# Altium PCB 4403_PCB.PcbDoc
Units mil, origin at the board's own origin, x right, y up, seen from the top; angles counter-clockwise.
Board outline 547.34 x 948.91 mil, 4 copper layers (Top Layer, Signal Layer 1, Signal Layer 2, Bottom Layer), stack 30.634 mil thick; 38 components, 56 nets, 193 pads, 89 vias.
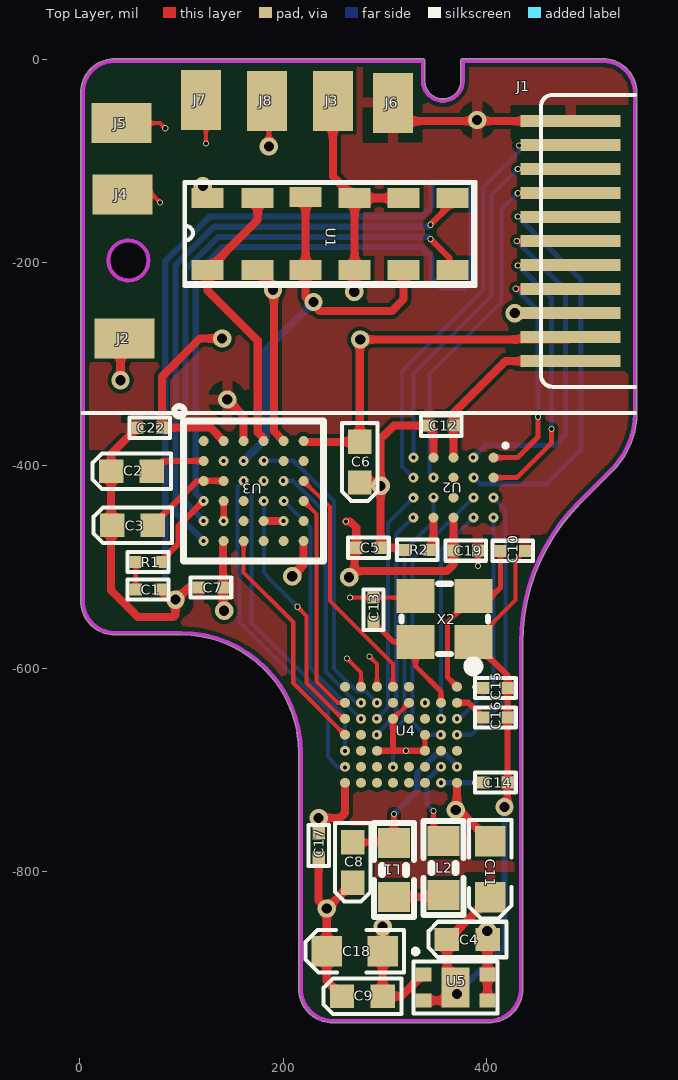
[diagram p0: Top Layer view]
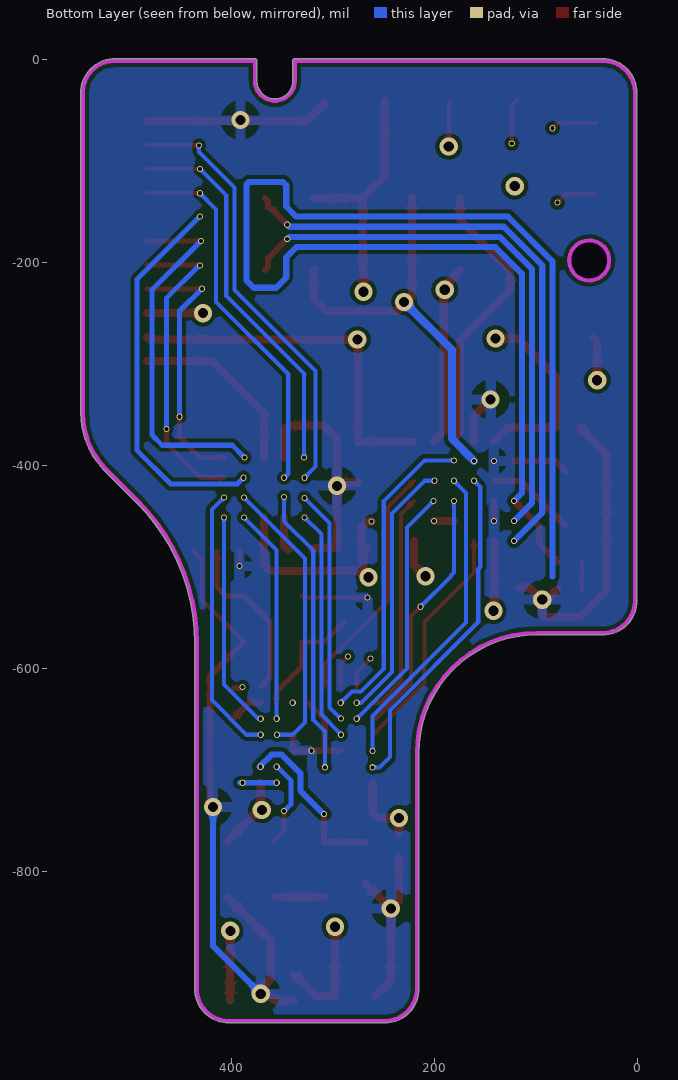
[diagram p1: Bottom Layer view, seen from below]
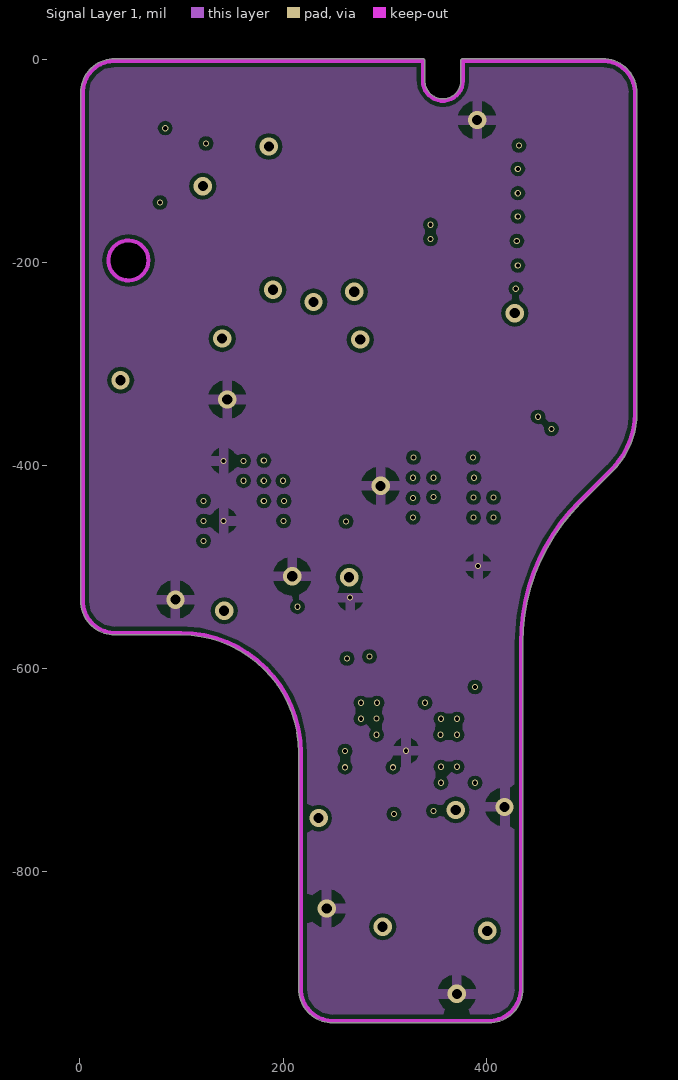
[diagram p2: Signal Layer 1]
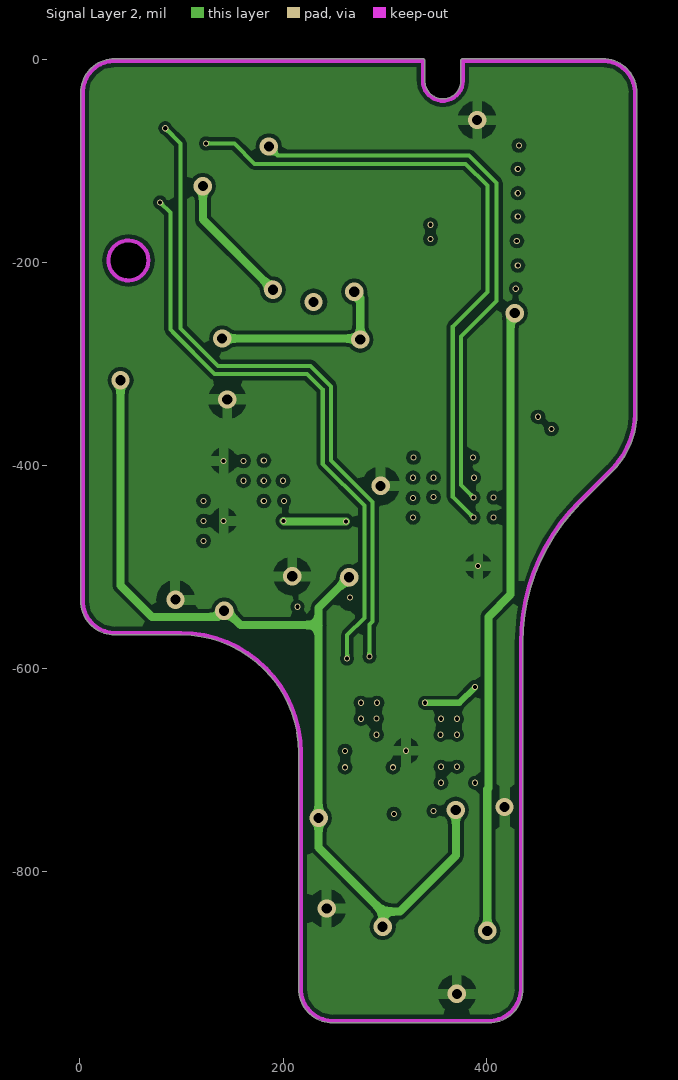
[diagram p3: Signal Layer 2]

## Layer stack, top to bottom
Top Solder: solder mask 0.4, Solder Resist, Dk 3.5
Top Layer: signal copper 1.4
Dielectric 1: core 10, FR-4, Dk 4.2
Signal Layer 1: signal copper 1.417
Dielectric 3: prepreg 5, Dk 4.2
Signal Layer 2: signal copper 1.417
Dielectric 4: core 10, Dk 4.2
Bottom Layer: signal copper 1.4
Bottom Solder: solder mask 0.4, Solder Resist, Dk 3.5

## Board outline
34.38,-566.67 99.34,-566.67 cw(c99.34,-682.77) 215.44,-682.77 215.44,-915.05 ccw(c248.95,-915.05) 248.95,-948.56 402.49,-948.56 ccw(c402.49,-915.05) 436,-915.05 ccw(c433.99,-915.05) 436,-915.03 436,-574.54 cw(c630.84,-574.54) 493.06,-436.79 cw(c630.84,-574.54) 493.07,-436.77 ccw(c491.64,-435.35) 493.08,-436.77 493.07,-436.77 524.56,-405.29 ccw(c467.45,-348.19) 548.21,-348.19 ccw(c546.19,-348.19) 548.21,-348.19 ccw(c546.19,-348.19) 548.21,-348.15 ccw(c546.19,-348.12) 548.21,-348.12 548.21,-33.16 ccw(c514.7,-33.16) 514.7,0.35 376.9,0.35 ccw(c376.9,-1.67) 374.89,-1.67 374.89,-21.35 ccw(c376.9,-21.35) 374.89,-21.37 ccw(c357.22,-21.35) 374.89,-21.35 374.89,-21.37 cw(c357.22,-21.35) 339.55,-21.35 339.55,-1.67 ccw(c337.53,-1.67) 337.53,0.35 34.38,0.35 ccw(c34.38,-33.16) 0.87,-33.16 ccw(c2.89,-33.16) 0.87,-33.18 0.87,-533.16 ccw(c34.38,-533.16)
cut-out: 47.77,-217.81 cw(c47.77,-198.12) 28.08,-198.12 cw(c47.77,-198.12) 47.77,-178.44 cw(c47.77,-198.12) 67.45,-198.12 cw(c47.77,-198.12)

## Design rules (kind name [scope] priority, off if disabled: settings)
Clearance [All] p1: gap=4 ignorepadtopadclearanceinfootprint=FALSE except(0: Arc-Hole Track-Hole SMDPad-Hole THPad-Hole Via-Hole Fill-Hole Poly-Hole Region-Hole Text-Hole)
DiffPairsRouting DiffPair_DiffPairsRouting [InDifferentialPair ('D_DET')] p1: maxlimit=4 minlimit=4 mostfreqgap=4 toplayer_minwidth=6 toplayer_maxwidth=6 toplayer_prefwidth=6 midlayer1_minwidth=6 midlayer1_maxwidth=6 midlayer1_prefwidth=6 midlayer2_minwidth=6 midlayer2_maxwidth=6 midlayer2_prefwidth=6 bottomlayer_minwidth=6 bottomlayer_maxwidth=6 bottomlayer_prefwidth=6 maxuncoupledlength=500
DiffPairsRouting DiffPair_DiffPairsRouting_1 [InDifferentialPair ('D_DET')] p2: maxlimit=4 minlimit=4 mostfreqgap=4 toplayer_minwidth=6 toplayer_maxwidth=6 toplayer_prefwidth=6 midlayer1_minwidth=6 midlayer1_maxwidth=6 midlayer1_prefwidth=6 midlayer2_minwidth=6 midlayer2_maxwidth=6 midlayer2_prefwidth=6 bottomlayer_minwidth=6 bottomlayer_maxwidth=6 bottomlayer_prefwidth=6 maxuncoupledlength=500
DiffPairsRouting DiffPair_DiffPairsRouting_3 [InDifferentialPair ('D_DET')] p3: maxlimit=4 minlimit=4 mostfreqgap=4 toplayer_minwidth=6 toplayer_maxwidth=6 toplayer_prefwidth=6 midlayer1_minwidth=6 midlayer1_maxwidth=6 midlayer1_prefwidth=6 midlayer2_minwidth=6 midlayer2_maxwidth=6 midlayer2_prefwidth=6 bottomlayer_minwidth=6 bottomlayer_maxwidth=6 bottomlayer_prefwidth=6 maxuncoupledlength=500
DiffPairsRouting DiffPairsRouting_1 [InDifferentialPair ('D_DET')] p4: maxlimit=10 minlimit=10 mostfreqgap=10 toplayer_minwidth=15 toplayer_maxwidth=15 toplayer_prefwidth=15 midlayer1_minwidth=15 midlayer1_maxwidth=15 midlayer1_prefwidth=15 midlayer2_minwidth=15 midlayer2_maxwidth=15 midlayer2_prefwidth=15 bottomlayer_minwidth=15 bottomlayer_maxwidth=15 bottomlayer_prefwidth=15 maxuncoupledlength=500
DiffPairsRouting DiffPair_DiffPairsRouting_2 [InDifferentialPair ('DET_')] p5: maxlimit=4 minlimit=4 mostfreqgap=4 toplayer_minwidth=6 toplayer_maxwidth=6 toplayer_prefwidth=6 midlayer1_minwidth=6 midlayer1_maxwidth=6 midlayer1_prefwidth=6 midlayer2_minwidth=6 midlayer2_maxwidth=6 midlayer2_prefwidth=6 bottomlayer_minwidth=6 bottomlayer_maxwidth=6 bottomlayer_prefwidth=6 maxuncoupledlength=500
DiffPairsRouting [All] p6: maxlimit=10 minlimit=10 mostfreqgap=10 toplayer_minwidth=15 toplayer_maxwidth=15 toplayer_prefwidth=15 midlayer1_minwidth=15 midlayer1_maxwidth=15 midlayer1_prefwidth=15 midlayer2_minwidth=15 midlayer2_maxwidth=15 midlayer2_prefwidth=15 bottomlayer_minwidth=15 bottomlayer_maxwidth=15 bottomlayer_prefwidth=15 maxuncoupledlength=500
MatchedLengths DiffPair_MatchedLengths [InDifferentialPair ('D_DET')] p1: tolerance=1000 checknetsindiffpair=FALSE checkdiffpairvsdiffpair=TRUE checkxsignals=TRUE checkothers=TRUE
MatchedLengths DiffPair_MatchedLengths_1 [InDifferentialPair ('D_DET')] p2: tolerance=1000 checknetsindiffpair=FALSE checkdiffpairvsdiffpair=TRUE checkxsignals=TRUE checkothers=TRUE
MatchedLengths DiffPair_MatchedLengths_3 [InDifferentialPair ('D_DET')] p3: tolerance=1000 checknetsindiffpair=FALSE checkdiffpairvsdiffpair=TRUE checkxsignals=TRUE checkothers=TRUE
MatchedLengths [InDifferentialPair ('D_DET')] p4: tolerance=1000 checknetsindiffpair=FALSE checkdiffpairvsdiffpair=TRUE checkxsignals=TRUE checkothers=TRUE
MatchedLengths DiffPair_MatchedLengths_2 [InDifferentialPair ('DET_')] p5: tolerance=1000 checknetsindiffpair=FALSE checkdiffpairvsdiffpair=TRUE checkxsignals=TRUE checkothers=TRUE
PolygonConnect [All] p1: connectstyle=Relief reliefconductorwidth=10 reliefentries=4 polygonreliefangle="90 Angle" airgapwidth=10
RoutingVias [All] p1: holewidth=28 width=50 viastyle="Through Hole" minholewidth=4 minwidth=10 maxholewidth=28 maxwidth=50
SolderMaskExpansion [All] p1: expansion=4 istentingtop=FALSE
Width [All] p1: maxlimit=100 minlimit=4 preferedwidth=10
29 further rules are at their usual default settings.

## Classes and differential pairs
component class 4403: C1 C2 C3 C5 C6 C7 C12 C19 C22 R1 R2 U1 U2
component class pca10040_sheet1_radio: C8 C10 C11 C13 C14 C15 C16 C17 L1 L2 U4 X2
component class POWER: C4 C9 C18 J1 J2 J3 J4 J5 J6 J7 J8 U5
differential pair D_DET: +DET_P -DET_N

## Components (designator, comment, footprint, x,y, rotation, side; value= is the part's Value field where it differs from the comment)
C1 "0.01uF" 0201 79,-522 r180 top
C2 "2.2uF" 0402 50.49,-405.25 r0 top
C3 "2.2uF" 0402 51.49,-458.25 r0 top
C4 "1.0uF" 0402 381,-866 r0 top
C5 "0.1uF" 0201 296,-481 r180 top
C6 "1.0uF" 0402 275,-397 r90 top
C7 "0.1uF" 0201 117,-520 r0 top
C8 "1.0uF" 0402 268,-791 r90 top
C9 "1.0uF" 0402 277.75,-921.74 r0 top
C10 "12pF" 0201 438,-484 r180 top
C11 "4.7" 0603 404,-825 r90 top
C12 "0.1uF" 0201 343.75,-360.74 r0 top
C13 "12pF" 0201 289,-530 r270 top
C14 "0.1uF" 0201 421,-712 r180 top
C15 "100pF" 0201 421,-619 r180 top
C16 "100pF" 0201 421,-648 r180 top
C17 "0.1uF" 0201 235,-786 r90 top
C18 "10uF" 0603 243,-878 r0 top
C19 "0.1uF" 0201 391.75,-483.74 r180 top
C22 "0.1uF" 0201 56.75,-362.74 r0 top
J1 "J11" J11 483,-61 r0 top
J2 "PAD" PAD1.5 43.75,-274.74 r0 top
J3 "PAD" PAD1.5 249,-41 r90 top
J4 "PAD" PAD1.5 42,-133 r0 top
J5 "PAD" PAD1.5 41,-63 r0 top
J6 "PAD" PAD1.5 308,-43 r90 top
J7 "PAD" PAD1.5 119,-40 r90 top
J8 "PAD" PAD1.5 184,-41 r90 top
L1 "15nH" INDC1608X06L 309,-798 r90 top
L2 "10uH" INDC1608X06L 358,-796 r270 top
R1 "1K" 0201 55,-495 r0 top
R2 "10K" 0201 320,-483 r0 top
U1 "SRH_7060" SRH_7060 125.75,-136.74 r90 top
U2 "TXB0108_YZP_20" BGA20C50P4X5_189X239X50 367.75,-421.74 r270 top
U3 "AFE4403" BGA36C50P6X6_304X304X50 171,-425 r0 top
U4 "NRF52832_WLCS" BGA56C40P7X8_300X320X38 316,-665 r270 top
U5 "XC6221A332GR" USP-4 369.75,-913.74 r0 top
X2 "32MHz" BT-XTAL_2016 359,-551 r0 top

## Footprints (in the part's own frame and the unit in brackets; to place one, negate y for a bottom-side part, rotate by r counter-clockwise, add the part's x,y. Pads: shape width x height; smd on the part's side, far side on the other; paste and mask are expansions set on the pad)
0201 [mil]
  rect 12x12 smd: 1(0,0) 2(24,0)
  silkscreen extent -8,-10 32,10, body extent 0,-6 24,6, height 12
0402 [mil]
  rect 24x23 smd: 1(-19.74,-0.49) 2(20.26,-0.49)
  silkscreen extent -38,-18 39,17, body extent -19,-10 21,10, height 20
0603 [mil]
  rect 30x30 smd: 1(0,0) 2(55,0)
  silkscreen extent -21,-21 76,21, body extent -4,-15 59,15, height 20
BGA20C50P4X5_189X239X50 [mm] "BGA, 20-Leads, Body 1.89x2.39mmx0.50mm, Pitch 0.50mm"
  round 0.25 smd: A1(-0.75,1) A2(-0.25,1) A3(0.25,1) A4(0.75,1) B1(-0.75,0.5) B2(-0.25,0.5) B3(0.25,0.5) B4(0.75,0.5) C1(-0.75,0) C2(-0.25,0) C3(0.25,0) C4(0.75,0) D1(-0.75,-0.5) D2(-0.25,-0.5) D3(0.25,-0.5) D4(0.75,-0.5) E1(-0.75,-1) E2(-0.25,-1) E3(0.25,-1) E4(0.75,-1)
  silkscreen extent -1.1,1.25 -1,1.35, body extent -0.94,-1.19 0.95,1.2, height 0.5
BGA36C50P6X6_304X304X50 [mm] "BGA, 0.5mm pitch, 6X6, 36 pins"
  round 0.25 smd: A1(-1.25,1.25) A2(-0.75,1.25) A3(-0.25,1.25) A4(0.25,1.25) A5(0.75,1.25) A6(1.25,1.25) B1(-1.25,0.75) B2(-0.75,0.75) B3(-0.25,0.75) B4(0.25,0.75) B5(0.75,0.75) B6(1.25,0.75) C1(-1.25,0.25) C2(-0.75,0.25) C3(-0.25,0.25) C4(0.25,0.25) C5(0.75,0.25) C6(1.25,0.25) D1(-1.25,-0.25) D2(-0.75,-0.25) D3(-0.25,-0.25) D4(0.25,-0.25) D5(0.75,-0.25) D6(1.25,-0.25) E1(-1.25,-0.75) E2(-0.75,-0.75) E3(-0.25,-0.75) E4(0.25,-0.75) E5(0.75,-0.75) E6(1.25,-0.75) F1(-1.25,-1.25) F2(-0.75,-1.25) F3(-0.25,-1.25) F4(0.25,-1.25) F5(0.75,-1.25) F6(1.25,-1.25)
  silkscreen extent -1.98,-1.75 1.75,2.12, body extent -1.52,-1.52 1.52,1.52, height 0.5
BGA56C40P7X8_300X320X38 [mm] "BGA, 20-Leads, Body 3.00x3.20mmx0.38mm, Pitch 0.40mm"
  round 0.25 smd: A1(-1.2,1.4) A2(-0.8,1.4) A3(-0.4,1.4) A4(0,1.4) A5(0.4,1.4) A6(0.8,1.4) A7(1.2,1.4) B2(-0.8,1) B3(-0.4,1) B4(0,1) B5(0.4,1) B6(0.8,1) B7(1.2,1) C2(-0.8,0.6) C3(-0.4,0.6) C4(0,0.6) C5(0.4,0.6) C6(0.8,0.6) C7(1.2,0.6) D1(-1.2,0.2) D2(-0.8,0.2) D3(-0.4,0.2) D6(0.8,0.2) D7(1.2,0.2) E1(-1.2,-0.2) E2(-0.8,-0.2) E3(-0.4,-0.2) E6(0.8,-0.2) E7(1.2,-0.2) F1(-1.2,-0.6) F2(-0.8,-0.6) F3(-0.4,-0.6) F4(0,-0.6) F5(0.4,-0.6) F6(0.8,-0.6) F7(1.2,-0.6) G1(-1.2,-1) G2(-0.8,-1) G3(-0.4,-1) G4(0,-1) G5(0.4,-1) G6(0.8,-1) G7(1.2,-1) H1(-1.2,-1.4) H2(-0.8,-1.4) H3(-0.4,-1.4) H4(0,-1.4) H5(0.4,-1.4) H6(0.8,-1.4) H7(1.2,-1.4)
  silkscreen extent -1.83,1.69 -1.59,1.93, body extent -1.5,-1.6 1.5,1.6, height 0.38
BT-XTAL_2016 [mm]
  rect 0.95x0.85 smd: 1(-0.725,-0.575) 2(0.725,-0.575) 3(0.725,0.575) 4(-0.725,0.575)
  silkscreen extent -1.08,-0.88 1.08,0.88, body extent -1.05,-0.85 1.05,0.85, height 0.56
INDC1608X06L [mm]
  rect 0.75x0.8 smd: 1(-0.675,0) 2(0.675,0)
  silkscreen extent -1.17,-0.5 1.17,0.5, body extent -0.8,-0.48 0.8,0.48, height 0.8
J11 [mm]
  rect 2.5x0.3 smd: 1(0,0) 2(0,-0.6) 3(0,-1.2) 4(0,-1.8) 5(0,-2.4) 6(0,-3) 7(0,-3.6) 8(0,-4.2) 9(0,-4.8) 10(0,-5.4) 11(0,-6)
PAD1.5 [mm]
  rect 1.5x1 smd: 1(0,0)
SRH_7060 [mm]
  rect 0.5x0.8 smd: 1(0,0) 2(0,-1.25) 3(0.025,-2.45) 4(0,-3.675) 5(0,-4.9) 6(0,-6.125) 7(-1.8,-6.125) 8(-1.8,-4.9) 9(-1.8,-3.675) 10(-1.8,-2.45) 11(-1.8,-1.25) 12(-1.8,0)
  silkscreen extent -2.2,-6.7 0.4,0.58
USP-4 [mm]
  rect 0.4x0.35 smd: 1(-0.8,0.325) 2(-0.8,-0.325) 3(0.8,-0.325) 4(0.8,0.325)
  rect 0.7x1 smd: 5(0,0)
  silkscreen extent -1.06,-0.65 1.05,0.96, body extent -0.8,-0.6 0.8,0.6, height 0.6

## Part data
C1 C2 C3 C4 C5 C6 C7 C8 C9 C10 C11 C12 C13 C14 C15 C16 C17 C18 C19 C22: "Capacitor, NP0, ±0.1pF"
L1 L2: "Inductor, 80mA, ±10%"
R1 R2: "Not mounted"
U2: "Imported"
U4: library part NRF52832_WLCSP
X2: "XTAL SMD 2016, 32MHz, Cl=8pF, Tol: ±10ppm, Stab: ±10ppm"

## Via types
v1: diameter 6, hole 4, Top Layer to Bottom Layer, tented both sides, 66 vias
v2: diameter 18, hole 10, Top Layer to Bottom Layer, tented both sides, 23 vias

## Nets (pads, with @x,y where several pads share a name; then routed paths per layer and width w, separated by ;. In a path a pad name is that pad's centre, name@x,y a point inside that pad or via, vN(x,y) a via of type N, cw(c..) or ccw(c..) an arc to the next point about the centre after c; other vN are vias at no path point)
4403_ADC_RDY: U3.D5 U4.G3 | length 245.6
  Bottom Layer w4: v1(201,-435) 227,-461 227,-599.62 v1(276.63,-649.25)
4403_AFE_P\D\N\: U3.C3 U4.H6 | length 332.5
  Bottom Layer w4: v1(161,-415) 155,-421 155,-500 157,-502 157,-554 244,-641 244,-687 254,-697 v1(261,-697)
4403_DIAG_END: U3.B4 U4.F2 | length 306.8
  Bottom Layer w4: v1(181,-395) 210,-395 250,-435 250,-599.99 272.51,-622.5 281.38,-622.5 v1(292.38,-633.5)
4403_R\E\S\E\T\: U3.D4 U4.H3 | length 248.9
  Top Layer w4: v1(214,-539) 223,-548 223,-614 258.25,-649.25 U4.H3
  Bottom Layer w4: v1(181,-435) 181,-505.4 184,-508.4 184,-509 v1(214,-539)
4403_SCLK: U3.C6 U4.E1 | length 239
  Top Layer w4: U3.C6 246,-440.94 246,-533.1 308.13,-595.23 U4.E1
4403_SET: U3.D6 U4.H2 | length 219.6
  Top Layer w4: U3.D6 233,-447.63 233,-612.69 253.82,-633.5 U4.H2
4403_SIMO: U3.C4 U4.H5 | length 309.1
  Bottom Layer w4: v1(181,-415) 169,-427 169,-554.69 261,-646.69 v1(261,-681)
4403_SOMI: U3.C5 U4.G2 | length 258.7
  Bottom Layer w4: v1(200,-415) 210,-415 242,-447 242,-603.31 272.2,-633.5 v1(276.63,-633.5)
+3.3V: C5.2 C7.2 C9.2 C11.2 C17.2 C18.2 C19.2 J2.1 U2.C4 U3.E4 U3.E5 U3.F2 U4.A7 U4.H7 U5.1 | length 1611.3
  Top Layer w8: v2(40,-316) 40,-278.49 J2.1 ; U3.F2@141,-474.69 C7.2 141,-542 v2(142,-543) ; U3.E4 v1(200.53,-454.53) ; C17.2 v2(235,-747) 256,-747 260.88,-742.12 U4.H7 ; v1(262,-455) 266,-455 272,-461 C5.2 270.37,-482.63 C5.2@270.37,-485.37 ; v2(265,-510) 265,-509 v2@270.37,-503.63 ; C5.2@266,-481 C5.2@270.37,-485.37 ; C9.2 316.48,-922.23 337.77,-900.94 U5.1 ; C9.2 C18.2 v2(298,-854) ; U2.C4 C19.2 367.75,-497.25 361.37,-503.63 v2@270.37,-503.63 ; U4.A7 371.12,-737.12 C11.2 ; v2@270.37,-503.63 C5.2@270.37,-485.37
  Signal Layer 2 w8: v2(40,-316) 40,-518 71,-549 136,-549 v2(142,-543) 144,-543 158,-557 235,-557 ; v1(200.53,-454.53) 201,-455 v1(262,-455) ; v2(265,-510) 235,-540 235,-557 ; v2(298,-854) 298,-839 ; v2(370,-739) 370,-784 315,-839 298,-839 ; 235,-557 v2(235,-747) 235,-776 298,-839
ACCL_INT0: J1.3 U2.E1 | length 378.8
  Top Layer w4: v1@431.24,-108.24 J1.3
  Bottom Layer w4: v1(328.38,-392.21) 328.38,-310.38 328,-310 405,-233 405,-134 v1(431,-108)
ACCL_INT0_52: U2.E4 U4.F4 | length 228.9
  Bottom Layer w4: v1(292,-665) 292,-664.56 311.38,-645.18 311.38,-467.62 v1(328,-451)
AFE_XIN: U3.F3 U4.H4 | length 232.1
  Top Layer w4: U3.F3 161.16,-505.16 210,-554 210,-614.12 U4.H4
AFE_XOUT: U3.F4
AP_WAKEUP_MCU: J1.2 U2.E2 | length 429.8
  Top Layer w4: v1@432.38,-84.62 J1.2
  Bottom Layer w4: v1(328,-412) 317,-401 317,-307 397,-227 397,-126.44 432,-91.44 v1(432,-85)
AP_WAKEUP_MCU_52: U2.E3 U4.F3 | length 232.2
  Bottom Layer w4: v1(292,-649) 292.44,-649 303.38,-638.06 303.38,-456.62 v1(328,-432)
DEC2: C16.2 U4.A2 | length 31.9
  Top Layer w6: U4.A2 382.5,-633.5 C16.2
DEC3: C15.2 U4.C2 | length 62.8
  Top Layer w6: v1@390,-619 C15.2
  Signal Layer 2 w6: v1(339.62,-633.5) 373.5,-633.5 v1(389,-618)
DET_N: U1.6 U3.F1 | length 585.7
  Top Layer w6: v1(345,-163) 363.89,-144.11 363.89,-139.74 U1.6
  Bottom Layer w6: v1(121.79,-474.21) 94,-446.43 94,-202.86 131.86,-165 343,-165 v1(345,-163)
DET_P: U1.7 U3.E1 | length 549.7
  Top Layer w6: v1(345,-177) 363.89,-195.89 363.89,-204.61 U1.7
  Bottom Layer w6: v1(121.79,-454.53) 104,-436.74 104,-207 136,-175 343,-175 v1(345,-177)
GND: C1.1 C2.1 C3.1 C4.1 C5.1 C6.1 C7.1 C8.1 C9.1 C10.1 C11.1 C12.1 C13.1 C14.1 C15.1 C16.1 C17.1 C18.1 C19.1 C22.1 J1.1 J6.1 R2.1 U2.D1 U3.A3 U3.B2 U3.D2 U3.E2 U3.F6 U4.C4 U4.C5 U4.D2 U4.E3 U4.F5 U5.2 U5.5 X2.2 X2.4 | length 1854.8
  Top Layer w4: v1(266,-530) C13.1 328.82,-530 X2.4 ; U4.E3 U4.D2 ; U4.C5 U4.C4 ; X2.2 428.95,-532.23 428.95,-493.05 C10.1 ; C19.1 391.75,-498.75 v1(392,-499)
  Top Layer w6: v1(141.47,-454.53) U3.D2 ; U4.F5 U4.C5 ; 308.13,-680.62 U4.E3 ; U4.C4@338.78,-665.84 U4.C4 ; X2.2 421,-607.09 C15.1 C16.1 C14.1 421,-733 v2(418,-736)
  Top Layer w8: C22.1 30.75,-388.74 C2.1 30.75,-522.75 57,-549 92,-549 94,-547 v2(94,-532) ; C1.1 89,-532 v2(94,-532) ; C7.1 107,-520 95,-532 v2(94,-532) ; v2(145,-335) 161.16,-351.16 U3.A3 ; v2(209,-509) 220.21,-497.79 U3.F6 ; C17.1 235,-828.23 v2@243,-836.23 ; C9.1 243,-907.22 C18.1 v2@243,-836.23 ; C8.1 v2@243,-836.23 ; C6.1 v2@296,-416.74 ; J6.1 326,-61 J1.1 ; R2.1 318,-481 C5.1 v2@296,-416.74 ; U5.2 356.95,-926.54 U5.5 361.26,-905.25 C4.1 362.51,-866.49 C11.1 ; U2.D1 348.06,-365.06 C12.1 309.26,-360.74 296,-374 v2@296,-416.74
  Bottom Layer w6: v2(371,-920) 418,-873 v2(418,-736)
  other v1: 321,-680.75 141.47,-395.47
  other v2: 243,-836 296,-420 391,-60
LED_DRV_SUP: C6.2 C22.2 J1.10 J3.1 U1.4 U1.5 U1.9 U3.A2 U3.A6 | length 987.2
  Top Layer w8: v2(140,-275) 118,-275 80.75,-312.25 C22.2 128.43,-362.74 U3.A2 ; U3.A6@221.16,-376.74 C6.2 275.49,-276.51 v2(276,-276) 480.6,-276 J1.10 ; J3.1 249,-115.31 U1.4 ; v2(270,-229) 270,-208.04 U1.9 U1.4 ; U1.5 U1.4
  Signal Layer 2 w8: v2@141,-276 v2(140,-275) 275,-275 v2(276,-276) 276,-235 v2(270,-229)
NetC1_2: C1.2 R1.1 | length 27
  Top Layer w4: C1.2 R1.1
NetC2_2: C2.2 U3.B1 | length 55.3
  Top Layer w6: C2.2 81.02,-395.47 U3.B1
NetC3_2: C3.2 U3.C1 U3.C2 | length 87.8
  Top Layer w6: C3.2 115.33,-415.16 U3.C1 U3.C2
NetC8_2: C8.2 L1.2 U4.A6 | length 172.6
  Top Layer w6: C8.2@268.49,-771.32 C8.2 L1.2@308.31,-770.74 ; L1.2 v1(309,-743)
  Bottom Layer w6: v1(309,-743) 332,-720 332,-702.9 350.4,-684.5 360.34,-684.5 372.34,-696.5 v1(371.12,-696.5)
NetC14_2: C14.2 U4.B7 | length 36.4
  Bottom Layer w5: v1(355.37,-712.24) v1@391.76,-712.24
  other v1: 389,-712.24
NetL1_1: L1.1 L2.2 | length 47
  Top Layer w8: L1.1 L2.2@356,-824.57
NetL2_1: L2.1 U4.B6 | length 85.8
  Top Layer w5: v1(348,-740) 348,-759.43 L2.1
  Bottom Layer w5: v1(348,-740) 341.5,-733.5 341.5,-709.85 354.85,-696.5 v1(355.37,-696.5)
NetR1_2: R1.2 U3.D1 | length 1369.4
  Top Layer w6: R1.2 97,-477 97,-459.63 v1(121.79,-434.84)
  Bottom Layer w6: 84,-509 84,-198.72 127.72,-155 336.03,-155 346,-145.03 346,-124 349,-121 383,-121 385,-123 385,-218 378,-225 356,-225 346,-215 346,-195 336,-185 140.14,-185 114,-211.14 114,-427.06 v1(121.79,-434.84)
NetR2_2: R2.2 U2.D4 | length 33.4
  Top Layer w8: R2.2 348.06,-478.94 U2.D4
P0.02: U4.C6
P0.05: U4.E7
P0.06: U4.F7
P0.08: U4.G7
P0.09: U4.G6
P0.10: U4.G5
P0.21: U4.H1
RXD: J1.6 U2.B1 | length 364
  Top Layer w5: v1(430,-179) 430.11,-179.11 J1.6
  Bottom Layer w5: v1(387,-392) 399,-380 468,-380 478,-370 478,-227 v1(430,-179)
RXD_52: J7.1 U2.B4 U4.B3 | length 899.9
  Top Layer w4: J7.1 124,-45 v1(124,-83)
  Signal Layer 2 w4: v1(124,-83) 152,-83 172,-103 379.69,-103 401,-124.31 401,-229 367,-263 367,-430.83 v1(387.43,-451.27)
  Bottom Layer w4: v1(355.37,-649.25) 355.37,-483.33 v1(387.43,-451.27)
SCL: J1.7 U2.A2 | length 311.8
  Top Layer w5: U2.A2 430.1,-411.9 464,-378 v1(464,-364) ; v1@431.27,-202.73 J1.7
  Bottom Layer w5: v1(431,-203) 431.73,-203 464,-235.27 v1(464,-364)
SCL_52: U2.A3 U4.A4 | length 266.3
  Bottom Layer w4: v1(371.12,-665) 385,-665 419,-631 419,-443.46 v1(407.12,-431.58)
SDA: J1.8 U2.A1 | length 261.5
  Top Layer w5: U2.A1 430.79,-392.21 451,-372 v1(451,-352) ; v1(429,-226) 429.35,-226.35 J1.8
  Bottom Layer w5: v1(429,-226) 451,-248 v1(451,-352)
SDA_52: U2.A4 U4.A3 | length 214.2
  Bottom Layer w4: v1(371.12,-649.25) 373.3,-649.25 407.12,-615.44 v1(407.12,-451.27)
SUB_INT: J1.4 U2.D2 | length 369.6
  Top Layer w4: v1@431.13,-131.87 J1.4
  Bottom Layer w4: v1(348,-412) 344,-408 344,-310 415,-239 415,-148 v1(431,-132)
SUB_INT_52: U2.D3 U4.E6 | length 282.6
  Bottom Layer w4: v1(308,-697) 308,-661.87 319.38,-650.49 319.38,-483.62 348,-455 v1(348,-431)
SWDCLK: J5.1 U4.F1 | length 736.9
  Top Layer w4: J5.1 79,-63 v1(84,-68) ; v1(285,-588) 292.38,-595.38 U4.F1
  Signal Layer 2 w4: v1(84,-68) 99,-83 99,-265 136,-302 227,-302 247,-322 247,-395 288,-436 288,-553.31 285,-556.31 v1(285,-588)
SWDIO: J4.1 U4.G1 | length 666.3
  Top Layer w4: J4.1 71,-133 v1(79,-141) ; v1(263,-590) 276.63,-603.63 U4.G1
  Signal Layer 2 w4: v1(79,-141) 89,-151 89,-266 91,-268 91,-268.31 132.69,-310 223.69,-310 239,-325.31 239,-398.31 280,-439.31 280,-550 263,-567 v1(263,-590)
TX_3: U1.3 U1.8 U1.10 U3.B3 | length 419.2
  Top Layer w8: U1.3 U1.10 222.2,-234.2 236,-248 307,-248 318.66,-236.34 U1.8
  Bottom Layer w8: v1(161.16,-395.47) 183,-373.63 183,-286 v2(230,-239)
TX_N: U1.1 U1.11 U3.A5 | length 309.4
  Top Layer w8: U1.11 191,-223.65 191,-366.26 U3.A5
  Signal Layer 2 w8: v2(121,-125) 121,-158 v2(190,-227)
TX_P: U1.2 U1.12 U3.A4 | length 282.3
  Top Layer w8: U1.2 174.96,-158.39 U1.12 125.75,-227.75 175,-277 175,-367.23 180.84,-373.07 U3.A4
TXD: J1.5 U2.B2 | length 376.8
  Bottom Layer w5: v1(388,-412) 394,-418 460,-418 493,-385 493,-217 v1(431,-155)
TXD_52: J8.1 U2.B3 U4.B4 | length 892.7
  Top Layer w4: J8.1 186,-43 v2(186,-86)
  Signal Layer 2 w4: v2(186,-86) 195,-95 383,-95 410,-122 410,-238 375,-273 375,-419.15 v1(387.43,-431.58)
  Bottom Layer w4: v1(355,-665) 339.62,-665 327.38,-652.76 327.38,-491.64 v1(387.43,-431.58)
VBAT: C4.2 J1.9 U5.3 U5.4 | length 734.2
  Top Layer w8: U5.3 U5.4 C4.2 ; v2(428,-250) J1.9
  Signal Layer 2 w8: v2(401,-858) 401,-718.63 402,-717.63 402,-549 424,-527 424,-254 v2(428,-250)
VDD2: C12.2 J1.11 U2.C1 | length 180.4
  Top Layer w8: U2.C1 C12.2 367.75,-348.25 418.78,-297.22 J1.11
XC1: C13.2 U4.B2 X2.1 | length 119.8
  Top Layer w5: C13.2 308.64,-573.64 X2.1 330.46,-597.46 355.37,-622.37 U4.B2
XC2: C10.2 U4.A1 X2.3 | length 169.7
  Top Layer w5: U4.A1 362,-608.64 362,-553.91 X2.3 405.64,-528.36 414,-520 C10.2
pads on no net: U2.C2 U2.C3 U3.A1 U3.B5 U3.B6 U3.D3 U3.E3 U3.E6 U3.F5 U4.A5 U4.B5 U4.C3 U4.C7 U4.D1 U4.D3 U4.D6 U4.D7 U4.E2 U4.F6 U4.G4

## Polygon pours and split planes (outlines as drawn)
GND on Top Layer "SL1_GND" (solid, remove dead copper, pour order 54): -58,49 -56,47 588,47 588,-1015 591,-1018 572,-1037 -96,-1037 -96,13 -65,44
GND on Signal Layer 1 "SL1_GND" (solid, remove dead copper, pour order 56): -70,-1028 -69,-1029 603,-1029 603,133 600,136 587,123 -74,123 -74,-1027 -73,-1028
GND on Signal Layer 2 "SL1_GND" (solid, remove dead copper, pour order 58): -56,52 -53,49 621,49 621,-1059 623,-1061 615,-1069 -51,-1069 -51,52 -55,56
GND on Bottom Layer "SL1_GND" (solid, remove dead copper, pour order 60): -49,56 -43,62 579,62 579,-1040 580,-1041 577,-1038 -50,-1038 -50,51

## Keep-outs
Keep-Out Layer:
  circle w4: c47.77,-198.12 r19.68
  lines w0.5: 2.89,-533.16 ccw(c34.38,-533.16) 34.38,-564.66 ; 217.45,-915.05 ccw(c248.95,-915.05) 248.95,-946.55 ; 402.49,-946.55 ccw(c402.49,-915.05) 433.99,-915.05
  lines w4: 2.89,-348.12 2.89,-533.16 ; 546.19,-348.12 546.19,-348.19 ; 2.89,-533.16 ccw(c34.38,-533.16) 34.38,-564.66 ; 2.89,-533.16 2.89,-33.16 cw(c34.38,-33.16) 34.38,-1.67 337.53,-1.67 337.53,-21.35 ccw(c357.22,-21.35) 376.9,-21.35 376.9,-1.67 514.7,-1.67 cw(c514.7,-33.16) 546.19,-33.16 546.19,-348.19 ; 34.38,-564.66 99.34,-564.66 ; 34.38,-564.66 99.34,-564.66 ; 99.34,-564.66 cw(c99.34,-682.77) 217.45,-682.77 ; 217.45,-915.05 ccw(c248.95,-915.05) 248.95,-946.55 ; 217.45,-915.05 217.45,-682.77 ; 217.45,-915.05 217.45,-682.77 ; 248.95,-946.55 402.49,-946.55 ; 248.95,-946.55 402.49,-946.55 ; 402.49,-946.55 ccw(c402.49,-915.05) 433.99,-915.05 ; 433.99,-915.05 433.99,-574.54 ; 433.99,-915.05 433.99,-574.54 ; 433.99,-574.54 cw(c630.84,-574.54) 491.64,-435.35 ; 491.64,-435.35 523.13,-403.86 ; 491.64,-435.35 523.13,-403.86 ; 523.13,-403.86 ccw(c467.45,-348.19) 546.19,-348.19

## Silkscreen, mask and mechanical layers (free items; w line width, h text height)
Top Overlay:
  lines w0.5: 105.14,-220.95 105.14,-122.53 388.61,-122.53 388.61,-220.95 105.14,-220.95
  lines w4: 2.89,-348.12 546.19,-348.12 ; 546.19,-322.53 465.48,-322.53 cw(c465.48,-310.72) 453.67,-310.72 453.67,-46.94 cw(c465.48,-46.94) 465.48,-35.13 546.19,-35.13 ; 103.28,-220.17 103.28,-121.75 386.74,-121.75 386.74,-220.17 103.28,-220.17
Mechanical 11:
  circle w0.25: c34.38,-1.67 r0.12
  circle w0.25: c248.95,-946.55 r0.12
  circle w0.25: c2.89,-33.16 r0.12
  circle w0.25: c546.19,-33.16 r0.12
  circle w0.25: c34.38,-1.67 r0.12
  circle w0.25: c34.38,-564.66 r0.12
  circle w0.25: c217.45,-915.05 r0.12
  circle w0.25: c433.99,-915.05 r0.12
  circle w0.25: c2.89,-533.16 r0.12
  circle w0.25: c217.45,-915.05 r0.12
  circle w0.25: c532.41,-60.72 r0.12
  circle w0.25: c433.99,-54.82 r0.12
  circle w0.25: c532.41,-54.82 r0.12
  circle w0.25: c532.41,-60.72 r0.12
